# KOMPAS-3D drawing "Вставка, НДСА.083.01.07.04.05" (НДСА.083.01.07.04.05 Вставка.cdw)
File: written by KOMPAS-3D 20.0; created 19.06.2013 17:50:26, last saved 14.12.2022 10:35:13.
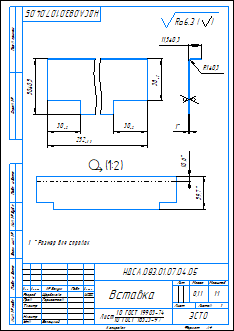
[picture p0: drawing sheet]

Sheet 1: A4, portrait

Document properties: Автор: otv; Знак неуказанной шероховатости: 4; Параметр неуказанной шероховатости: Ra6.3; Полное имя файла: НДСА.083.01.07.04.05 Вставка.m3d; PLM_CDWXDTO: <item xmlns="http://appius.ru/pdm" xmlns:xs="http://www.w3.org/2001/XMLSchema" xmlns:xsi="http://www.w3.org/2001/XMLSchema-instance" xsi:type="item">  <element xmlns:d2p1="http://v8.1c.ru/8.1/data/enterprise/current-config" xsi:type="d2p1:CatalogRef.aps_Элемен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; Масса: 0.112325; PDM_DOCXDTO: <item xmlns="http://appius.ru/pdm" xmlns:xs="http://www.w3.org/2001/XMLSchema" xmlns:xsi="http://www.w3.org/2001/XMLSchema-instance" xsi:type="item">  <element xmlns:d2p1="http://v8.1c.ru/8.1/data/enterprise/current-config" xsi:type="d2p1:CatalogRef.aps_Элемен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; PDM_ITEMXDTO: <item xmlns="http://appius.ru/pdm" xmlns:xs="http://www.w3.org/2001/XMLSchema" xmlns:xsi="http://www.w3.org/2001/XMLSchema-instance" xsi:type="item">  <element xmlns:d2p1="http://v8.1c.ru/8.1/data/enterprise/current-config" xsi:type="d2p1:CatalogRef.aps_Элемен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; PDM_DRAWINGXDTO: <item xmlns="http://appius.ru/pdm" xmlns:xs="http://www.w3.org/2001/XMLSchema" xmlns:xsi="http://www.w3.org/2001/XMLSchema-instance" xsi:type="item">  <element xmlns:d2p1="http://v8.1c.ru/8.1/data/enterprise/current-config" xsi:type="d2p1:CatalogRef.aps_Элемен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

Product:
- Part/product: Вставка  | designation НДСА.083.01.07.04.05
    Масса: 0.112325
    additional columns: <item xmlns="http://appius.ru/pdm" xmlns:xs="http://www.w3.org/2001/XMLSchema" x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; <item xmlns="http://appius.ru/pdm" xmlns:xs="http://www.w3.org/2001/XMLSchema" x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; <item xmlns="http://appius.ru/pdm" xmlns:xs="http://www.w3.org/2001/XMLSchema" x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
    source file: НДСА.083.01.07.04.05 Вставка.cdw

Title block, sheet 1: Наименование: Вставка; designation: НДСА.083.01.07.04.05; Материал: Лист 1.0 ГОСТ 19903-74 10 ГОСТ 16523-97; Масса: 0,11; scale: 1:1; Количество листов документа: 1; organisation: ЭСТО; Форматы листов документа: A4; stored path: C:\Пищагина\Чертежи Ялика\УКРД.839.01.06.04.03 - Вставка.cdw; Разработал: Щербакова; Проверил: Горностаев; Утвердил: Белецкий; Разработал, date: 14.12.2022
Table, sheet 1:
  6;Sortament:VBE6DDF60DAD111D69930000021274E8E;Material:VDE12371B5FDD453AAD3A0896F0FE5778^SortamentEx:V81C504E77C80471490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

Views: Спереди 1, Спереди, Проекционный вид 2, Вид 3, Развертка
Referenced files in C:\Users\cherbakova\Desktop\Виноград\Новая папка (4)\: НДСА.083.01.07.04.05 Вставка.m3d
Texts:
  Ra6.3
  Ra6.3 ( )
  НДСА.083.01.07.04.05 Вставка
Dimensions and other numbers on the sheet: 252; 50±0,5; 30; 38; 1±0,3; 11,5±0,3; 59,7; 10,6; 1:1; 0,11; 14.12.2022

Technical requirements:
  *Размер для справок.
